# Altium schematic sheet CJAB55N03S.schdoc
size 127 x 101 mm
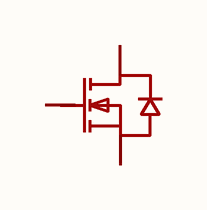
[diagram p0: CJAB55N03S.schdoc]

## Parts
Q?  cjab55n03s  [WDFN-8_L3.0-W3.0-P0.65-LS3.3-BL-EP]  (value not drawn)

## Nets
NetQ?_1: Q?.1(S) Q?.2(S) Q?.3(S)
NetQ?_5: Q?.5(D) Q?.6(D) Q?.7(D) Q?.8(D) Q?.9(D)

Not connected (* = marked no-connect by the designer): Q? 4(G)

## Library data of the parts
Q? = cjab55n03s: 数量:1个N沟道;漏源电压(Vdss):30V;连续漏极电流(Id):55A;导通电阻(RDS(on)):9.5mΩ@4.5V;耗散功率(Pd):40W;阈值电压(Vgs(th)):2.5V;; Manufacturer: CJ(江苏长电/长晶); AddInBom: yes; ModelId: f591fab4cccc4a76ab0e2fbf775bdd2c; ModelTransform: 129.921,129.921,0,0,0,0,0,-3.15,0; Number: 1个N沟道; Drain to Source Voltage: 30V; Current - Continuous Drain(Id): 55A; Pd - Power Dissipation: 40W; Gate Threshold Voltage (Vgs(th)): 2.5V; Gate Charge(Qg): 50nC@10V; Input Capacitance(Ciss): 2.8nF; Reverse Transfer Capacitance (Crss@Vds): 240pF; Type: N沟道; Output Capacitance(Coss): 295pF; Vgs: ±20V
